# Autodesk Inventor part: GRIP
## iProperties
Created: 2010-11
Part Number: GRIP
Document SubType Name: Modeling
Designer: ROBERT
Density: 1 g/cm^3
Author: ROBERT
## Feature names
1. Extrusion1
2. Extrusion2
3. Fillet1
